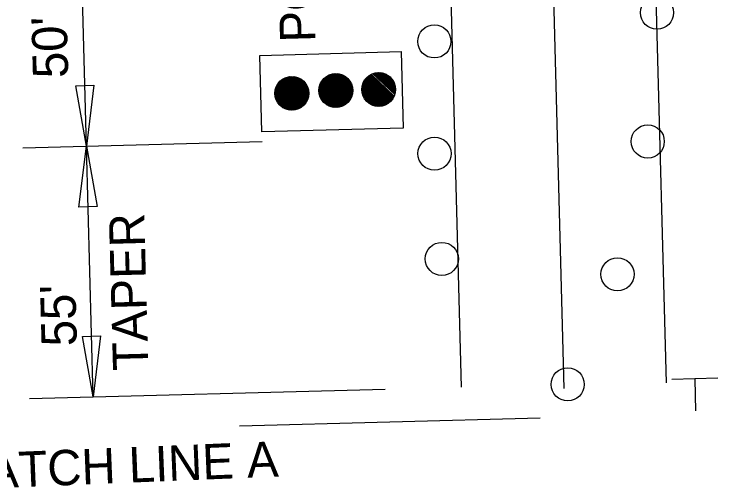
# Model space of a CAD drawing. Extents: x 1929624 to 1932072, y 596315 to 605533.
# Drawn here: x 1930138.7 to 1930260.9, y 598509 to 598591.7 of the extents above; entities that cross this region are included whole.
import ezdxf

# ---------------------------------------------------------------- set-up
doc = ezdxf.new("R2010")
doc.units = 0
doc.layers.add('Default', color=7, linetype='Continuous')

msp = doc.modelspace()

# ---------------------------------------------------------------- linework, layer by layer
at = {"layer": 'Default'}
for p, q in [((1930251.95, 598527.64), (1930247.82, 598681.69)), ((1930234.18, 598526.67), (1930230.15, 598676.96)), ((1930216.38, 598526.91), (1930212.41, 598675)), ((1930151.22, 598568.73), (1930150.3, 598603.17)), ((1930189.51, 598576.57), (1930185.41, 598580.45)), ((1930189.57, 598576.69), (1930185.53, 598580.52)), ((1930189.62, 598576.82), (1930185.65, 598580.58)), ((1930189.67, 598576.95), (1930185.78, 598580.63)), ((1930189.71, 598577.08), (1930185.91, 598580.68)), ((1930189.75, 598577.22), (1930186.05, 598580.73)), ((1930189.78, 598577.37), (1930186.2, 598580.77)), ((1930189.8, 598577.52), (1930186.35, 598580.8)), ((1930189.82, 598577.68), (1930186.51, 598580.82)), ((1930189.83, 598577.85), (1930186.67, 598580.84)), ((1930189.83, 598578.03), (1930186.85, 598580.85)), ((1930189.81, 598578.22), (1930187.04, 598580.84)), ((1930189.78, 598578.42), (1930187.25, 598580.83)), ((1930189.74, 598578.64), (1930187.47, 598580.79)), ((1930189.66, 598578.89), (1930187.72, 598580.73)), ((1930189.54, 598579.19), (1930188.02, 598580.62)), ((1930196.72, 598576.41), (1930192.45, 598580.45)), ((1930196.8, 598576.5), (1930192.54, 598580.54)), ((1930196.88, 598576.6), (1930192.63, 598580.63)), ((1930196.96, 598576.71), (1930192.73, 598580.71)), ((1930197.03, 598576.82), (1930192.84, 598580.78)), ((1930197.09, 598576.93), (1930192.95, 598580.86)), ((1930197.16, 598577.04), (1930193.06, 598580.93)), ((1930197.22, 598577.17), (1930193.18, 598580.99)), ((1930197.27, 598577.29), (1930193.3, 598581.05)), ((1930197.32, 598577.42), (1930193.43, 598581.11)), ((1930197.36, 598577.56), (1930193.56, 598581.16)), ((1930197.4, 598577.7), (1930193.7, 598581.2)), ((1930197.43, 598577.84), (1930193.84, 598581.24)), ((1930197.45, 598578), (1930194, 598581.27)), ((1930197.47, 598578.16), (1930194.16, 598581.3)), ((1930197.48, 598578.33), (1930194.32, 598581.32)), ((1930197.48, 598578.5), (1930194.5, 598581.32)), ((1930197.46, 598578.69), (1930194.69, 598581.32)), ((1930197.43, 598578.9), (1930194.9, 598581.3)), ((1930197.38, 598579.12), (1930195.12, 598581.26)), ((1930197.31, 598579.37), (1930195.37, 598581.2)), ((1930197.19, 598579.66), (1930195.67, 598581.1)), ((1930196.96, 598580.05), (1930196.08, 598580.89)), ((1930204.01, 598576.46), (1930199.75, 598580.5)), ((1930204.1, 598576.55), (1930199.83, 598580.6)), ((1930204.19, 598576.65), (1930199.92, 598580.69)), ((1930204.27, 598576.75), (1930200.02, 598580.78)), ((1930204.35, 598576.85), (1930200.11, 598580.86)), ((1930204.42, 598576.95), (1930200.22, 598580.94)), ((1930204.49, 598577.06), (1930200.32, 598581.02)), ((1930204.56, 598577.18), (1930200.43, 598581.09)), ((1930204.62, 598577.3), (1930200.55, 598581.15)), ((1930204.68, 598577.42), (1930200.67, 598581.22)), ((1930204.77, 598577.68), (1930200.92, 598581.33)), ((1930204.81, 598577.82), (1930201.06, 598581.38)), ((1930204.85, 598577.96), (1930201.2, 598581.42)), ((1930204.88, 598578.11), (1930201.35, 598581.46)), ((1930204.9, 598578.27), (1930201.5, 598581.48)), ((1930204.91, 598578.43), (1930201.67, 598581.51)), ((1930204.91, 598578.6), (1930201.84, 598581.52)), ((1930204.91, 598578.79), (1930202.02, 598581.52)), ((1930204.89, 598578.98), (1930202.22, 598581.51)), ((1930204.85, 598579.19), (1930202.43, 598581.49)), ((1930204.79, 598579.43), (1930202.67, 598581.44)), ((1930204.7, 598579.69), (1930202.93, 598581.36)), ((1930204.54, 598580.01), (1930203.27, 598581.22)), ((1930204.13, 598580.58), (1930203.85, 598580.85)), ((1930149.36, 598579.23), (1930152.52, 598579.31)), ((1930151.22, 598568.73), (1930149.36, 598579.23)), ((1930152.52, 598579.31), (1930151.22, 598568.73)), ((1930188.36, 598575.36), (1930184.27, 598579.24)), ((1930188.48, 598575.43), (1930184.33, 598579.36)), ((1930188.59, 598575.5), (1930184.4, 598579.47)), ((1930188.69, 598575.58), (1930184.47, 598579.58)), ((1930188.79, 598575.66), (1930184.55, 598579.69)), ((1930188.89, 598575.75), (1930184.63, 598579.79)), ((1930188.98, 598575.84), (1930184.71, 598579.88)), ((1930189.07, 598575.93), (1930184.8, 598579.98)), ((1930189.15, 598576.03), (1930184.89, 598580.07)), ((1930189.23, 598576.13), (1930184.99, 598580.15)), ((1930189.31, 598576.23), (1930185.09, 598580.23)), ((1930189.38, 598576.34), (1930185.19, 598580.31)), ((1930189.44, 598576.45), (1930185.3, 598580.38)), ((1930189.31, 598579.58), (1930188.43, 598580.41)), ((1930195.51, 598575.61), (1930191.71, 598579.21)), ((1930195.65, 598575.66), (1930191.76, 598579.34)), ((1930195.77, 598575.71), (1930191.81, 598579.47)), ((1930195.9, 598575.77), (1930191.86, 598579.6)), ((1930196.01, 598575.84), (1930191.92, 598579.72)), ((1930196.13, 598575.91), (1930191.98, 598579.84)), ((1930196.24, 598575.98), (1930192.05, 598579.95)), ((1930196.34, 598576.06), (1930192.12, 598580.06)), ((1930196.44, 598576.14), (1930192.19, 598580.16)), ((1930196.54, 598576.22), (1930192.27, 598580.26)), ((1930196.63, 598576.31), (1930192.36, 598580.36)), ((1930202.87, 598575.78), (1930199.13, 598579.33)), ((1930203.01, 598575.83), (1930199.17, 598579.47)), ((1930203.14, 598575.88), (1930199.21, 598579.6)), ((1930203.26, 598575.94), (1930199.26, 598579.73)), ((1930203.38, 598576), (1930199.32, 598579.85)), ((1930203.5, 598576.07), (1930199.38, 598579.97)), ((1930203.61, 598576.14), (1930199.45, 598580.09)), ((1930203.72, 598576.21), (1930199.51, 598580.2)), ((1930203.82, 598576.29), (1930199.59, 598580.3)), ((1930203.92, 598576.37), (1930199.67, 598580.41)), ((1930187.27, 598574.99), (1930183.95, 598578.13)), ((1930187.43, 598575.02), (1930183.97, 598578.29)), ((1930187.58, 598575.05), (1930184, 598578.45)), ((1930187.73, 598575.09), (1930184.03, 598578.59)), ((1930187.86, 598575.13), (1930184.06, 598578.73)), ((1930188, 598575.18), (1930184.11, 598578.87)), ((1930188.12, 598575.24), (1930184.16, 598579)), ((1930188.25, 598575.3), (1930184.21, 598579.12)), ((1930194.92, 598575.46), (1930191.6, 598578.61)), ((1930194.75, 598575.45), (1930191.6, 598578.44)), ((1930194.57, 598575.44), (1930191.6, 598578.26)), ((1930194.38, 598575.44), (1930191.61, 598578.07)), ((1930195.08, 598575.49), (1930191.62, 598578.77)), ((1930195.23, 598575.52), (1930191.64, 598578.92)), ((1930195.37, 598575.56), (1930191.68, 598579.07)), ((1930202.26, 598575.65), (1930199.03, 598578.71)), ((1930202.09, 598575.64), (1930199.03, 598578.54)), ((1930201.91, 598575.64), (1930199.04, 598578.36)), ((1930202.43, 598575.67), (1930199.05, 598578.88)), ((1930201.71, 598575.65), (1930199.06, 598578.16)), ((1930202.58, 598575.7), (1930199.07, 598579.04)), ((1930202.73, 598575.74), (1930199.09, 598579.19)), ((1930187.1, 598574.97), (1930183.95, 598577.96)), ((1930186.92, 598574.97), (1930183.95, 598577.79)), ((1930186.73, 598574.97), (1930183.96, 598577.6)), ((1930186.53, 598574.99), (1930183.99, 598577.39)), ((1930186.3, 598575.02), (1930184.04, 598577.17)), ((1930186.05, 598575.09), (1930184.12, 598576.92)), ((1930194.18, 598575.46), (1930191.64, 598577.87)), ((1930193.95, 598575.5), (1930191.69, 598577.64)), ((1930193.7, 598575.56), (1930191.76, 598577.4)), ((1930193.4, 598575.67), (1930191.89, 598577.11)), ((1930201.49, 598575.68), (1930199.1, 598577.95)), ((1930201.25, 598575.73), (1930199.16, 598577.71)), ((1930200.98, 598575.81), (1930199.26, 598577.44)), ((1930200.64, 598575.96), (1930199.43, 598577.11)), ((1930185.76, 598575.19), (1930184.24, 598576.63)), ((1930185.35, 598575.4), (1930184.46, 598576.24)), ((1930193, 598575.87), (1930192.11, 598576.71)), ((1930140.19, 598568.44), (1930181.76, 598569.55)), ((1930149.93, 598558.15), (1930151.22, 598568.73)), ((1930152.39, 598525.19), (1930151.22, 598568.73)), ((1930151.22, 598568.73), (1930153.09, 598558.24)), ((1930153.09, 598558.24), (1930149.93, 598558.15)), ((1930150.53, 598535.69), (1930153.69, 598535.77)), ((1930152.39, 598525.19), (1930150.53, 598535.69)), ((1930153.69, 598535.77), (1930152.39, 598525.19)), ((1930252.87, 598528.27), (1930260.88, 598528.49)), ((1930256.86, 598528.26), (1930257, 598522.8)), ((1930141.36, 598524.89), (1930203.09, 598526.55)), ((1930177.83, 598520.17), (1930230.03, 598521.57))]:
    msp.add_line(p, q, dxfattribs=at)
msp.add_lwpolyline([(1930181.71, 598571.19), (1930181.36, 598584.48), (1930205.88, 598585.14), (1930206.24, 598571.85)], close=True, dxfattribs=at)
for centre, radius in [((1930250.3, 598591.91), 2.88), ((1930211.64, 598586.92), 2.88), ((1930186.89, 598577.91), 2.94), ((1930194.54, 598578.38), 2.94), ((1930201.97, 598578.58), 2.94), ((1930248.69, 598569.55), 2.88), ((1930211.66, 598567.43), 2.88), ((1930212.94, 598549.15), 2.88), ((1930243.43, 598546.48), 2.88), ((1930234.79, 598527.37), 2.88)]:
    msp.add_circle(centre, radius, dxfattribs=at)

# ---------------------------------------------------------------- texts
for s, height, rotation, p in [('PORTABLE TRAFFIC SIGNAL SYSTEM', 6.1396, 91.5377, (1930191, 598586.83)), ("50'", 6.14, 91.5377, (1930148.09, 598580.62)), ('TAPER', 6.14, 91.5377, (1930161.99, 598529.82)), ("  55' ", 6.14, 91.5377, (1930149.71, 598529.49)), ('MATCH LINE A', 6.1396, 2.3436, (1930127.24, 598509.02))]:
    msp.add_text(s, height=height, rotation=rotation, dxfattribs=at).set_placement(p)

doc.saveas('drawing.dxf')
